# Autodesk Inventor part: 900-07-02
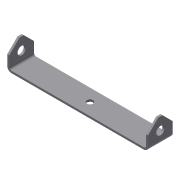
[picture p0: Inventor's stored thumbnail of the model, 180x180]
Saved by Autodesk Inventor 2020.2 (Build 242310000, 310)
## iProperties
Created: 2015-11
Part Number: 900-07-02
Material: Ogólny
Document SubType Name: Konstrukcja blachowa
Designer: F.Stasiak
Mass: 987.147 g
Surface Area: 2199.36 cm^2
Volume: 987.147 cm^3
Density: 1 g/cm^3
Sheet Metal Rule: Domyślne
Appearance: Domyślna
Catalog Web Link: www.expertbooks.pl
Manager: www.cadconsulting.pl
Company: Fabian Stasiak CAD Consulting
Author: F.Stasiak
Subject: Zbiór ćwiczeń. Autodesk Inventor 2020. Kurs Professional
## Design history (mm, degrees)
sketch "Szkic1"
  geometry: L1 (-342, 60)-(342, 60); L2 (342, 60)-(342, -60); L3 (342, -60)-(-342, -60); L4 (-342, -60)-(-342, 60); L5 (-342, 60)-(342, -60); L6 (342, 60)-(-342, -60); C1 r 15 at (0, 0); 1 further point
  constraints: 12 end point, 2 midpoint, 2 parallel, 1 centre point, 1 coincident, 1 horizontal, 1 perpendicular
  dimensions: "d0" = 684 distance of L2.end L3.end; "d1" = 120 distance of L1.end L2.end; "d2" = 30 diameter of C1
extrude "Wyciągnięcie proste1" new body sketch "Szkic1" distance "d3" = 10; taper "d4" = 0 deg
node "Kołnierz1"
feature "Fazowanie narożnika1" dims "d15" = 50, "d16" = 6, angle "d17" = 45 deg
sketch "Szkic3"
  geometry: L1 (100, 70)-(100, 50) reference; 3 further points
  constraints: 1 horizontal alignment, 1 midpoint
  dimensions: "d18" = 60 distance from line of L1 point (40, 60)
hole "Otwór1" sketch "Szkic3" at (40, 60) diameter "d19" = 40; stored, may be unused: countersink angle "d23" = 90 deg, drill point angle "d25" = 118 deg; dims "d20" = 6, "d21" = 4, "d22" = 2, "d24" = 10 (= Grubość)
node "Bryła1"
sketch "Szkic2"
  geometry: L1 (0, 120)-(-120, 120); L2 (-120, 120)-(-120, 0); 1 other entity
  constraints: 4 end point, 4 other
feature "Płyta1" dims "d5" = 10 (= SzerokośćGięciaPodcięcia), "d6" = 5 (= GłębokośćGięciaPodcięcia), "d7" = 20 (= MinimalnaPozostałość), "d8" = 10 (= PromieńGięcia), "d9" = 120, "d10" = 90 deg, "d11" = 10 (= PromieńGięcia), "d12" = 40 (= RozmiarPodcięciaNarożnika), "d13" = 10 (= Wielk_odstępu), "d14" = 10 (= Rozmiar_promienia_Jacobiego), "d26" = 10 (= Grubość), "OdstępPołączenia" = 0.01
feature "Gięcie1" dims "d5" = 10 (= SzerokośćGięciaPodcięcia), "d6" = 5 (= GłębokośćGięciaPodcięcia), "d7" = 20 (= MinimalnaPozostałość), "d8" = 10 (= PromieńGięcia), "d9" = 120, "d10" = 90 deg, "d11" = 10 (= PromieńGięcia), "d26" = 10 (= Grubość), "OdstępPołączenia" = 0.01
feature "Narożnik1" dims "d9" = 120, "d10" = 90 deg, "d12" = 40 (= RozmiarPodcięciaNarożnika), "d13" = 10 (= Wielk_odstępu), "d14" = 10 (= Rozmiar_promienia_Jacobiego)
other parameters: "Grubość" = 10 (derived), "WspółczynnikK" = 4.4, "PromieńGięcia" = 10 (= Grubość), "GłębokośćGięciaPodcięcia" = 5 (= 0.5 x Grubość)
